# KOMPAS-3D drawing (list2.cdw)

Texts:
  ТОТС.ОППТС.00.000.Д2
  Графическая модель производственного цикла ремонта трактора Т-150К в сете- вом исполнении. Таблица расчетов сете- вого графика. Распределение работ меж- ду исполнителями
  Текст на чертеже
  Размерные надписи
  Шероховатость
  Линия-выноска #1
  Линия-выноска #2
  Линия-выноска #3
  Отклонения формы и база
  Заголовок таблицы
  Ячейка таблицы
  Стрелка вида
  Обозначение изменения
  Фигурная скобка
  Номер узла
  Марка координационной оси
  VRCB
  Выносная надпись
  Обозначение узла
  Марка/позиционное обозначение с линией-выноской
  Марка/позиционное обозначение на линии
  Марка/позиционное обозначение без линии-выноски
  Табельный номер
  рабочего
  Распределение работ между исполнителями
  Symbol type A
  Графическая модель производственного цикла
  ремонта трактора Т-150К  в сетевом исполнении
  Резерв
  времени
  Поздний срок
  свершения
  события
  Ранний срок
  Длитель-
  ность
  работы
  Кол-во ис-
  полнителей
  Трудоем-
  кость
  Код
  Наименование работ
  чел.
  чел.-ч.
  Подготовка трактора к ремонту
  Диагностирование
  Снять электрооборудование, кабину, радиатор,
  агрегаты гидросистемы
  .Разборка, ремонт сборка радиатора, гидроситемы
  Разборка, ремонт, сборка электрооборудования
  Снятие двигателя, топливного бака,м-мов
  управления
  Расборка ходовой части на агрегаты
  Текущий ремонт заднего моста и КП
  Разборка ремонт и сборка колёс
  Установка двигателя
  Установка колёс
  Установка радиатора, гидросистемы
  Установка электрооборудования, кабины
  Обкатка и устранение неисправностей
  Мойка деталей
  Установка КП
  Установка топл. бака и м-ма управления
  Дефектация и комплектация
  Разборка, ремонт, сборка топл. бак. и управл
  tц =48,5 ч.
  Всего
  Ерофеев В.В
  ЧГАУ, кафедра ТОТС
  гр. 442
  ТОТС.ОППТС.00.000.Д2-
  Графическая модель производственного
  цикла ремонта трактора Т-150К в сете-
  вом исполнении. Таблица расчетов сете-
  вого графика. Распределение работ меж-
  ду исполнителями
Dimensions and other numbers on the sheet: 7; 1; 2; 3; 4; 5; 6; 8; 9; 10; 11; 12; 13; 14; 15; 16; 17; 18; 19; 20; 21; 22; 23; 24; 25; 26; 27; 28; 29; 30; 31; 32; 0-1; 1-2; 2-3; 3-6; 3-4; 6-9; 3-5; 6-7; 6-8; 9-10; 10-11; 33; 34; 35; 36; 37; 38; 39; 40; 41; 42; 43; 11-13; 13-15; 13-14; 15-16; 16-17; 11-12; 44; 45; 46; 47; 48; 49; 50; 17-18; 18-19; 0; 3,0; 3,5; 5,0; 6,0; 4,0; 8,0; 2,5; 1,5; 6,5; 10,5; 18,5; 48,5; 14,5; 32,5; 15,5; 19,5; 49,5; 21,5; 36,5; 20,5; 26,5; 30,5; 34,5; 39,5; 38,5; 44,5; 85,5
